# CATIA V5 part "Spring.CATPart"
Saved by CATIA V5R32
Part number: Part1
Bounding box of the stored display mesh (mm): x -50 to 50, y -44.999 to 44.983, z -4.984 to 154.984
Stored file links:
  D:\PROJECTS\Project 2022\CATIA V5 6R 2022\Resources\Input file\c19_catia_v5_6r2022_inp\c19_catia_v5_6r2022_inp\c19_catia_v5_6r2022_inp\C19_tut_01.CATPart\Spring.CATPart
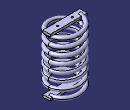
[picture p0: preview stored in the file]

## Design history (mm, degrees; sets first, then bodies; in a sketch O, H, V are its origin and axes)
Body1 (main body)
  Point1: (0, 0, 0)
  Point2: (0, 0, 150)
  Line1: type PtPt, FirstPoint Point2, SecondPoint Point1
  Point3: (40, 0, 0)
  Helix1: Direction Line1, RefPoint Point3, Pitch 20, Height 150, TaperAngle 0, Revolutions 1
  Plane1: type Normal, Curve Helix1, RefPoint vertex of Helix1, Ratio 0
  Sketch1 on Plane1, origin (0, -11.8615, 0.9439), H (1, 0, 0), V (0, 0.0793, 0.9968)
    circle A1 centre (-40, 149.5273) radius 5
    point P1 (-40, 149.5273)
    reference projected point E1 (-40, 149.5273) from vertex of Helix1
    radius A1 = 5
    coincidence: P1 E1
  Rib1: profile Sketch1, centre curve Helix1
  Sketch2 on xy-plane, origin (0, 0, 0), H (1, 0, 0), V (0, 1, 0)
    line L1 (-50, 10) -> (50, 10)
    line L2 (50, 10) -> (50, -10)
    line L3 (50, -10) -> (-50, -10)
    line L4 (-50, -10) -> (-50, 10)
    length L1 = 100
    distance L1 L3 = 20
    horizontal: L1 H, L3 H
    vertical: L2 V, L4 V
    symmetry: L3 L1 H, L2 L4 V
  Pad1: profile Sketch2, direction (0, 0, 1), length 3, mirrored extent
  Sketch3 on start face of Pad1, origin (0, 0, -3), H (1, 0, 0), V (0, -1, 0)
    circle A1 centre (-24.223, 0) radius 2.5
    point P1 (-24.223, 0)
    circle A2 centre (24.223, 0) radius 2.5
    point P2 (24.223, 0)
    radius A2 = 2.5
    coincidence: P1 H, P2 H
    symmetry: A2 A1 V
  Pocket1: profile Sketch3, direction (0, 0, 1), length 3
  Plane2: type Offset, RefPlane xy-plane, Offset 150
  Sketch4 on Plane2, origin (0, 0, 150), H (1, 0, 0), V (0, 1, 0)
    line L1 (-50, 10) -> (50, 10)
    line L2 (50, 10) -> (50, -10)
    line L3 (50, -10) -> (-50, -10)
    line L4 (-50, -10) -> (-50, 10)
    reference projected line E1 (50, -10) -> (50, 10) from edge [face of Pad1 from Sketch2.L2 | end face of Pad1]
    reference projected line E2 (-50, 10) -> (-50, -10) from edge [face of Pad1 from Sketch2.L4 | end face of Pad1]
    reference projected line E3 (-50, -10) -> (50, -10) from edge [face of Pad1 from Sketch2.L3 | end face of Pad1]
    reference projected line E4 (50, 10) -> (-50, 10) from edge [face of Pad1 from Sketch2.L1 | end face of Pad1]
    horizontal: L1 H, L3 H
    vertical: L2 V, L4 V
    coincidence: L2 E1, L4 E2, E3 L3, L1 E4
  Pad2: profile Sketch4, direction (0, 0, 1), length 3, mirrored extent
  Sketch5 on end face of Pad2, origin (0, 0, 153), H (1, 0, 0), V (0, 1, 0)
    circle A1 centre (-20.0406, 0) radius 2.5674
    point P1 (-20.0406, 0)
    circle A2 centre (20.0406, 0) radius 2.5674
    coincidence: P1 H
    symmetry: A1 A2 V
  Pocket2: profile Sketch5, direction (0, 0, -1), through (limit type 6)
